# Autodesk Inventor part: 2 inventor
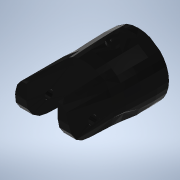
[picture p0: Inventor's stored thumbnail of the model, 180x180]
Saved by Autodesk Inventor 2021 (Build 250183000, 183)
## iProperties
Created: 2022-10
Part Number: 2 inventor
Material: Genérico
Document SubType Name: Modeling
Designer: Yair Obed
Density: 1 g/cm^3
Appearance: Valor por defecto
Author: Yair Obed
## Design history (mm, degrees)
node "2"
  node "MeshFeature1"
